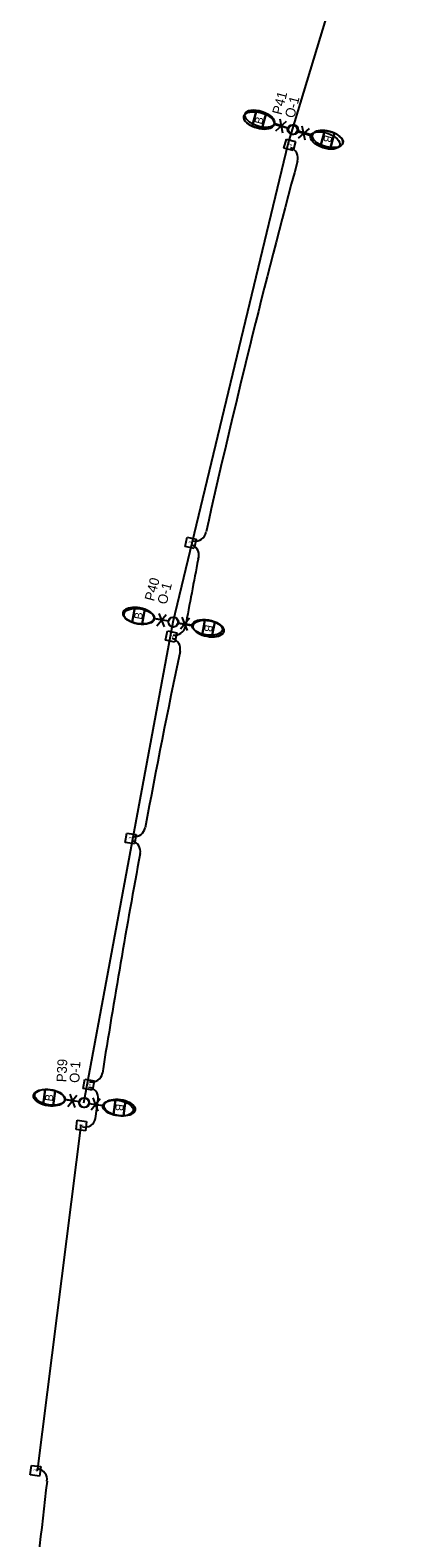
# Model space of a CAD drawing. Extents: x 925407 to 930994, y 604905 to 637063.
# Drawn here: x 929640 to 929836, y 615127 to 615898 of the extents above; entities that cross this region are included whole.
import ezdxf

# ---------------------------------------------------------------- set-up
doc = ezdxf.new("R2010")
doc.units = 0
for name, color, linetype in [('ActivePointCell_dp', 7, 'Continuous'), ('Conduit', 7, 'Continuous'), ('ConduitOT', 7, 'Continuous'), ('LiteCond_ep', 7, 'Continuous'), ('Miscellaneous2', 7, 'Continuous'), ('Miscellaneous9', 7, 'Continuous'), ('PoleLight', 7, 'Continuous'), ('PoleLight_ep', 7, 'Continuous'), ('PullBox', 7, 'Continuous')]:
    doc.layers.add(name, color=color, linetype=linetype)

msp = doc.modelspace()

# ---------------------------------------------------------------- linework, layer by layer
at = {"layer": 'Conduit'}
for p, q in [((929771.65, 615840.13), (929836, 616053.28)), ((929643.62, 615162.28), (929665.81, 615338.11))]:
    msp.add_line(p, q, dxfattribs=at)
at = {"layer": 'ConduitOT'}
msp.add_line((929673.1, 615341.51), (929674.57, 615351.36), dxfattribs=at)
for centre, radius, start, end in [((929771.22, 615832.87), 5.5, 342.25849, 72.38878), ((934163.46, 614649.51), 4543.37, 164.92456, 167.38776), ((929724.29, 615642.41), 5.5, 259.54672, 350.31391), ((934186.63, 614766.27), 4543.37, 169.07162, 169.51405), ((929720.57, 615629.71), 5.5, 337.55313, 67.83333), ((929713.75, 615594.28), 5.5, 261.58991, 347.9901), ((929711.06, 615581.71), 5.5, 346.32486, 75.69639), ((934164.07, 614652.78), 4543.37, 168.21893, 169.37919), ((929693.14, 615491.22), 5.5, 264.90919, 348.8746), ((929690.6, 615478.21), 5.5, 349.0415, 72.43777), ((934163.83, 614652.14), 4543.37, 169.53784, 170.97757), ((929671.29, 615365.72), 5.5, 257.80245, 348.56964), ((929669.1, 615351.98), 5.5, 353.5821, 84.34929), ((929667.71, 615342.62), 5.5, 257.80245, 348.56964), ((929642.91, 615156.82), 5.5, 352.03362, 82.80081), ((934160.74, 614626.29), 4543.37, 173.30395, 174.26654)]:
    msp.add_arc(centre, radius, start, end, dxfattribs=at)
at = {"layer": 'LiteCond_ep'}
for p, q in [((929712.91, 615595.53), (929771.65, 615840.13)), ((929667.26, 615349.62), (929712.91, 615595.53)), ((929643.43, 615161.29), (929643.56, 615162.28))]:
    msp.add_line(p, q, dxfattribs=at)
at = {"layer": 'Miscellaneous2'}
for p, q in [((929755.39, 615856.5), (929753.37, 615849.1)), ((929755.39, 615856.5), (929755.39, 615856.5)), ((929758.29, 615847.76), (929760.31, 615855.16)), ((929760.31, 615855.16), (929760.31, 615855.16)), ((929790.46, 615846.95), (929788.45, 615839.56)), ((929790.46, 615846.95), (929790.46, 615846.95)), ((929793.37, 615838.22), (929795.38, 615845.61)), ((929795.38, 615845.61), (929795.38, 615845.61)), ((929693.37, 615602.97), (929691.99, 615595.43)), ((929693.37, 615602.97), (929693.37, 615602.97)), ((929697, 615594.51), (929698.39, 615602.05)), ((929698.39, 615602.05), (929698.39, 615602.05)), ((929729.13, 615596.38), (929727.74, 615588.85)), ((929729.13, 615596.38), (929729.13, 615596.38)), ((929732.75, 615587.92), (929734.14, 615595.46)), ((929734.14, 615595.46), (929734.14, 615595.46)), ((929647.49, 615356.35), (929646.4, 615348.76)), ((929647.49, 615356.35), (929647.49, 615356.35)), ((929651.45, 615348.04), (929652.53, 615355.63)), ((929652.53, 615355.63), (929652.53, 615355.63)), ((929683.47, 615351.21), (929682.39, 615343.63)), ((929683.47, 615351.21), (929683.47, 615351.21)), ((929687.44, 615342.91), (929688.52, 615350.49)), ((929688.52, 615350.49), (929688.52, 615350.49))]:
    msp.add_line(p, q, dxfattribs=at)
for centre, major_axis, start_param, end_param in [((929756.84, 615852.13), (7.79, -2.12), 1.249648, 1.891946), ((929756.84, 615852.13), (7.79, -2.12), 4.391241, 4.391271), ((929756.84, 615852.13), (7.79, -2.12), 4.391271, 5.033538), ((929791.92, 615842.58), (7.79, -2.12), 1.249648, 1.891946), ((929791.92, 615842.58), (7.79, -2.12), 4.391241, 4.391271), ((929791.92, 615842.58), (7.79, -2.12), 4.391271, 5.033538), ((929695.19, 615598.74), (7.94, -1.46), 1.249648, 1.891946), ((929695.19, 615598.74), (7.94, -1.46), 4.391241, 4.391271), ((929695.19, 615598.74), (7.94, -1.46), 4.391271, 5.033538), ((929730.94, 615592.15), (7.94, -1.46), 1.249648, 1.891946), ((929730.94, 615592.15), (7.94, -1.46), 4.391241, 4.391271), ((929730.94, 615592.15), (7.94, -1.46), 4.391271, 5.033538), ((929649.47, 615352.19), (8, -1.14), 1.249648, 1.891946), ((929685.46, 615347.06), (8, -1.14), 1.249648, 1.891946), ((929649.47, 615352.19), (8, -1.14), 4.391241, 4.391271), ((929649.47, 615352.19), (8, -1.14), 4.391271, 5.033538), ((929685.46, 615347.06), (8, -1.14), 4.391241, 4.391271), ((929685.46, 615347.06), (8, -1.14), 4.391271, 5.033538)]:
    msp.add_ellipse(centre, major_axis=major_axis, ratio=0.5, start_param=start_param, end_param=end_param, dxfattribs=at)
at = {"layer": 'PoleLight'}
for p, q in [((929753.37, 615849.1), (929755.39, 615856.5)), ((929760.31, 615855.16), (929758.29, 615847.76)), ((929771.94, 615848.02), (929764.63, 615850.01)), ((929776.81, 615846.69), (929784.12, 615844.71)), ((929788.45, 615839.56), (929790.46, 615846.95)), ((929795.38, 615845.61), (929793.37, 615838.22)), ((929691.99, 615595.43), (929693.37, 615602.97)), ((929698.39, 615602.05), (929697, 615594.51)), ((929710.58, 615595.9), (929703.13, 615597.28)), ((929715.55, 615594.99), (929722.99, 615593.62)), ((929727.74, 615588.85), (929729.13, 615596.38)), ((929734.14, 615595.46), (929732.75, 615587.92)), ((929646.4, 615348.76), (929647.49, 615356.35)), ((929652.53, 615355.63), (929651.45, 615348.04)), ((929664.96, 615349.98), (929657.47, 615351.05)), ((929682.39, 615343.63), (929683.47, 615351.21)), ((929688.52, 615350.49), (929687.44, 615342.91)), ((929669.96, 615349.27), (929677.46, 615348.2))]:
    msp.add_line(p, q, dxfattribs=at)
for centre in [(929774.38, 615847.36), (929774.38, 615847.36), (929713.06, 615595.45), (929713.06, 615595.45), (929667.46, 615349.63), (929667.46, 615349.63)]:
    msp.add_circle(centre, 2.52, dxfattribs=at)
for centre, major_axis in [((929756.84, 615852.13), (7.79, -2.12)), ((929791.92, 615842.58), (7.79, -2.12)), ((929695.19, 615598.74), (7.94, -1.46)), ((929730.94, 615592.15), (7.94, -1.46)), ((929649.47, 615352.19), (8, -1.14)), ((929685.46, 615347.06), (8, -1.14))]:
    msp.add_ellipse(centre, major_axis=major_axis, ratio=0.5, dxfattribs=at)
for centre, major_axis, start_param, end_param in [((929756.84, 615852.13), (7.79, -2.12), 1.891945, 4.391241), ((929756.84, 615852.13), (7.79, -2.12), 0.847605, 1.249648), ((929756.84, 615852.13), (7.79, -2.12), 0, 0.847605), ((929756.84, 615852.13), (7.79, -2.12), 5.033538, 6.283185), ((929791.92, 615842.58), (7.79, -2.12), 1.891945, 4.391241), ((929791.92, 615842.58), (7.79, -2.12), 0.847605, 1.249648), ((929791.92, 615842.58), (7.79, -2.12), 0, 0.847605), ((929791.92, 615842.58), (7.79, -2.12), 5.033538, 6.283185), ((929695.19, 615598.74), (7.94, -1.46), 1.891945, 4.391241), ((929695.19, 615598.74), (7.94, -1.46), 5.033538, 6.283185), ((929695.19, 615598.74), (7.94, -1.46), 0.847605, 1.249648), ((929695.19, 615598.74), (7.94, -1.46), 0, 0.847605), ((929730.94, 615592.15), (7.94, -1.46), 1.891945, 4.391241), ((929730.94, 615592.15), (7.94, -1.46), 5.033538, 6.283185), ((929730.94, 615592.15), (7.94, -1.46), 0.847605, 1.249648), ((929730.94, 615592.15), (7.94, -1.46), 0, 0.847605), ((929649.47, 615352.19), (8, -1.14), 1.891945, 4.391241), ((929649.47, 615352.19), (8, -1.14), 5.033538, 6.283185), ((929649.47, 615352.19), (8, -1.14), 0.847605, 1.249648), ((929649.47, 615352.19), (8, -1.14), 0, 0.847605), ((929685.46, 615347.06), (8, -1.14), 1.891945, 4.391241), ((929685.46, 615347.06), (8, -1.14), 0.847605, 1.249648), ((929685.46, 615347.06), (8, -1.14), 5.033538, 6.283185), ((929685.46, 615347.06), (8, -1.14), 0, 0.847605)]:
    msp.add_ellipse(centre, major_axis=major_axis, ratio=0.5, start_param=start_param, end_param=end_param, dxfattribs=at)
at = {"layer": 'PoleLight_ep'}
for p, q in [((929765.38, 615846.84), (929770.88, 615851.71)), ((929767.39, 615852.87), (929768.87, 615845.67)), ((929771.56, 615848.17), (929764.59, 615850.5)), ((929776.21, 615846.63), (929783.18, 615844.3)), ((929782.39, 615847.97), (929776.89, 615843.09)), ((929780.38, 615841.93), (929778.9, 615849.13)), ((929710.49, 615595.91), (929703.23, 615597.07)), ((929704.61, 615593.59), (929709.24, 615599.29)), ((929705.61, 615599.87), (929708.24, 615593.01)), ((929721.2, 615597.47), (929716.58, 615591.76)), ((929720.2, 615591.19), (929717.57, 615598.05)), ((929715.33, 615595.14), (929722.59, 615593.99)), ((929664.84, 615350.01), (929657.58, 615351.16)), ((929658.96, 615347.68), (929663.59, 615353.39)), ((929659.96, 615353.97), (929662.59, 615347.1)), ((929675.56, 615351.57), (929670.93, 615345.86)), ((929674.56, 615345.28), (929671.93, 615352.15)), ((929669.68, 615349.24), (929676.94, 615348.09))]:
    msp.add_line(p, q, dxfattribs=at)
for centre in [(929773.88, 615847.4), (929712.91, 615595.53), (929667.26, 615349.62)]:
    msp.add_circle(centre, 2.45, dxfattribs=at)
for centre, major_axis in [((929757.15, 615852.97), (-7.44, 2.48)), ((929790.62, 615841.83), (7.44, -2.48)), ((929695.49, 615598.3), (-7.74, 1.23)), ((929730.33, 615592.76), (7.74, -1.23)), ((929649.84, 615352.39), (-7.74, 1.23)), ((929684.68, 615346.85), (7.74, -1.23))]:
    msp.add_ellipse(centre, major_axis=major_axis, ratio=0.5, dxfattribs=at)
at = {"layer": 'PullBox'}
for p, q in [((929769.55, 615837.91), (929770.81, 615842.59)), ((929774.22, 615836.65), (929769.55, 615837.91)), ((929770.81, 615842.59), (929775.48, 615841.33)), ((929775.48, 615841.33), (929774.22, 615836.65)), ((929718.95, 615634.21), (929719.99, 615638.94)), ((929719.99, 615638.94), (929724.72, 615637.9)), ((929724.72, 615637.9), (929723.68, 615633.17)), ((929723.68, 615633.17), (929718.95, 615634.21)), ((929709.04, 615586.24), (929710.08, 615590.98)), ((929710.08, 615590.98), (929714.81, 615589.94)), ((929714.81, 615589.94), (929713.77, 615585.2)), ((929713.77, 615585.2), (929709.04, 615586.24)), ((929688.37, 615482.79), (929689.19, 615487.56)), ((929693.15, 615481.97), (929688.37, 615482.79)), ((929689.19, 615487.56), (929693.96, 615486.75)), ((929693.96, 615486.75), (929693.15, 615481.97)), ((929666.85, 615356.85), (929667.67, 615361.62)), ((929667.67, 615361.62), (929672.44, 615360.81)), ((929672.44, 615360.81), (929671.63, 615356.03)), ((929671.63, 615356.03), (929666.85, 615356.85)), ((929663.22, 615335.83), (929663.84, 615340.64)), ((929668.02, 615335.21), (929663.22, 615335.83)), ((929663.84, 615340.64), (929668.65, 615340.01)), ((929668.65, 615340.01), (929668.02, 615335.21)), ((929639.75, 615159.27), (929640.37, 615164.07)), ((929644.55, 615158.64), (929639.75, 615159.27)), ((929640.37, 615164.07), (929645.18, 615163.45)), ((929645.18, 615163.45), (929644.55, 615158.64))]:
    msp.add_line(p, q, dxfattribs=at)

# ---------------------------------------------------------------- texts
at = {"layer": 'ActivePointCell_dp'}
for s, rotation, p in [('P41', 75.18661, (929768.28, 615854.64)), ('O-1', 75.18661, (929774.76, 615852.93)), ('P40', 75.18661, (929703.02, 615605.88)), ('O-1', 75.18661, (929709.49, 615604.17)), ('P39', 86.9991, (929658.18, 615359.99)), ('O-1', 86.9991, (929664.87, 615359.64))]:
    msp.add_text(s, height=5, rotation=rotation, dxfattribs=at).set_placement(p)
at = {"layer": 'Miscellaneous9'}
for rotation, p in [(74.77056, (929758.32, 615849.8)), (254.77056, (929790.44, 615844.92)), (79.56023, (929696.86, 615596.54)), (259.56023, (929729.27, 615594.36)), (81.88183, (929651.23, 615350.06)), (261.88183, (929683.7, 615349.19))]:
    msp.add_text('B', height=4.08, rotation=rotation, dxfattribs=at).set_placement(p)
at = {"layer": 'PullBox'}
for rotation, p in [(74.91653, (929773.28, 615838.73)), (77.62156, (929722.64, 615635.2)), (77.62156, (929712.73, 615587.24)), (80.30163, (929692.01, 615483.96)), (80.30163, (929670.49, 615358.01)), (82.58017, (929666.81, 615337.14)), (82.58017, (929643.34, 615160.58))]:
    msp.add_text('J', height=1.94, rotation=rotation, dxfattribs=at).set_placement(p)

doc.saveas('drawing.dxf')
